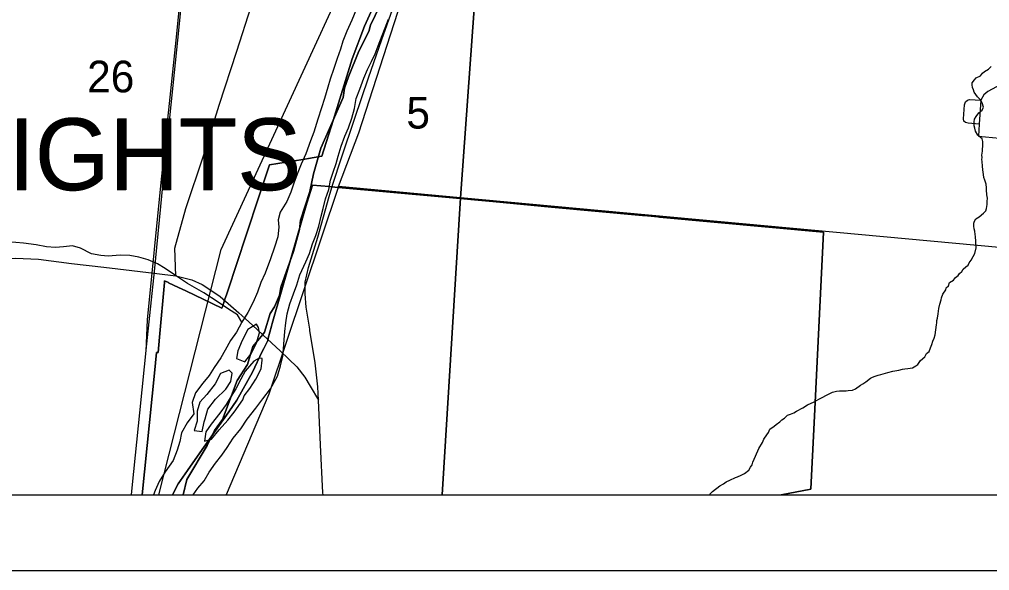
# Model space of a CAD drawing. Extents: x -38.1 to 35.9, y -2.7 to 28.5.
# Drawn here: x 9.239 to 10.521, y 12.831 to 13.559 of the extents above; entities that cross this region are included whole.
import ezdxf

# ---------------------------------------------------------------- set-up
doc = ezdxf.new("R2010")
doc.units = 0
for name, color, linetype in [('GM_X_City_Street', 7, 'Continuous'), ('GM_X_City_Street_Text', 7, 'Continuous'), ('GM_X_Corporation', 7, 'Continuous'), ('GM_X_Minor_River', 7, 'Continuous'), ('GM_X_Section', 7, 'Continuous'), ('GM_X_Township_Road', 7, 'Continuous'), ('GM_X_Township_Subdivision', 7, 'Continuous'), ('GM_X_US_Route', 7, 'Continuous'), ('SH_Border', 7, 'Continuous'), ('SH_Data', 7, 'Continuous')]:
    doc.layers.add(name, color=color, linetype=linetype)

msp = doc.modelspace()

# ---------------------------------------------------------------- linework, layer by layer
at = {"layer": 'GM_X_City_Street'}
for points in [[(9.4453, 13.22), (9.444, 13.2564), (9.4587, 13.3089), (9.4818, 13.3782), (9.5028, 13.4454), (9.5259, 13.5168), (9.5448, 13.5755), (9.5616, 13.6259), (9.57, 13.6511), (9.5825, 13.7036), (9.5952, 13.7624), (9.6045, 13.8015), (9.609, 13.8423), (9.6092, 13.8484)], [(10.5412, 13.4757), (10.5181, 13.4635), (10.5128, 13.4588), (10.509, 13.4517), (10.5066, 13.4204), (10.506, 13.4042), (10.5892, 13.3966)], [(10.5066, 13.4204), (10.492, 13.4214), (10.4888, 13.4225), (10.4866, 13.4243), (10.4862, 13.4271), (10.4875, 13.4459), (10.4886, 13.4497), (10.4911, 13.4517), (10.4938, 13.4527), (10.509, 13.4517)]]:
    msp.add_lwpolyline(points, dxfattribs=at)
at = {"layer": 'GM_X_City_Street_Text'}
msp.add_line((9.5328, 13.1674), (9.5467, 13.1547), dxfattribs=at)
for points in [[(9.6481, 13.3246), (9.6527, 13.3409), (9.6643, 13.3758), (9.6821, 13.428), (9.6998, 13.4814), (9.7174, 13.5322), (9.7316, 13.5717), (9.7554, 13.6313), (9.7764, 13.6835), (9.7943, 13.7255), (9.8058, 13.7523), (9.822, 13.7775), (9.8255, 13.7807)], [(9.6223, 13.1497), (9.6175, 13.1785), (9.6163, 13.1964), (9.6163, 13.2115), (9.6206, 13.2311), (9.6331, 13.2711), (9.6481, 13.3246)], [(9.1477, 13.2079), (9.1622, 13.217), (9.1854, 13.2292), (9.2042, 13.2375), (9.2179, 13.2418), (9.2336, 13.2434), (9.2638, 13.2418), (9.3078, 13.2364), (9.3504, 13.2313), (9.3871, 13.2268), (9.4204, 13.2231), (9.4453, 13.22)], [(9.4453, 13.22), (9.4666, 13.2146), (9.4801, 13.2087), (9.4969, 13.1975)], [(9.4969, 13.1975), (9.5041, 13.1928), (9.5287, 13.1712), (9.5328, 13.1674)], [(9.5467, 13.1547), (9.5605, 13.142), (9.5837, 13.1205), (9.6055, 13.1), (9.616, 13.0862), (9.623, 13.0741), (9.6337, 13.0559)], [(9.6337, 13.0559), (9.6331, 13.0735), (9.6297, 13.105), (9.6226, 13.1479), (9.6223, 13.1497)], [(9.64, 12.9308), (9.6398, 12.9336), (9.6365, 12.997), (9.6337, 13.0559)]]:
    msp.add_lwpolyline(points, dxfattribs=at)
at = {"layer": 'GM_X_Corporation'}
for points in [[(9.3869, 12.9308), (9.3883, 12.9446), (9.3979, 13.039), (9.4073, 13.1301), (9.4172, 13.2255), (9.4287, 13.3431), (9.4481, 13.5311), (9.4733, 13.7801), (9.4904, 13.9481), (9.5034, 14.0746), (9.5088, 14.1303), (9.5136, 14.1747), (9.5172, 14.2088), (9.5214, 14.251), (9.5248, 14.2842), (9.5323, 14.3467)], [(9.4062, 13.1203), (9.4081, 13.1617), (9.4262, 13.3434), (9.4457, 13.5313), (9.4708, 13.7803), (9.4879, 13.9484), (9.5009, 14.0749), (9.5064, 14.1306), (9.5111, 14.1749), (9.5147, 14.2091), (9.519, 14.2513), (9.5223, 14.2845), (9.5299, 14.347)]]:
    msp.add_lwpolyline(points, dxfattribs=at)
at = {"layer": 'GM_X_Section'}
for points in [[(10.4936, 13.2371), (10.4963, 13.2408), (10.4987, 13.2453), (10.501, 13.2495), (10.5027, 13.257), (10.5025, 13.2654), (10.5019, 13.2719), (10.5016, 13.2745), (10.5009, 13.2791), (10.5002, 13.2822), (10.4999, 13.2856), (10.4996, 13.2894), (10.5004, 13.292), (10.5024, 13.295), (10.5066, 13.298), (10.5124, 13.3028), (10.5155, 13.3058), (10.5163, 13.3088), (10.5172, 13.3141), (10.5173, 13.3183), (10.5177, 13.3225), (10.517, 13.3267), (10.5164, 13.3335), (10.5165, 13.3362), (10.5158, 13.3408), (10.514, 13.3461), (10.513, 13.3499), (10.5123, 13.3538), (10.5117, 13.3599), (10.511, 13.3648), (10.5107, 13.3709), (10.5104, 13.3736), (10.5105, 13.3762), (10.5102, 13.3793), (10.511, 13.3846), (10.5116, 13.3937), (10.5117, 13.3975), (10.5106, 13.4009), (10.508, 13.4032), (10.505, 13.4056), (10.5021, 13.411), (10.501, 13.4148), (10.5003, 13.4182), (10.5001, 13.4232), (10.5005, 13.427), (10.5029, 13.4303), (10.5064, 13.4352), (10.5106, 13.4385), (10.5126, 13.4427), (10.5108, 13.4484), (10.5079, 13.4527), (10.5045, 13.4565), (10.5023, 13.4592), (10.5001, 13.4623), (10.4994, 13.4654), (10.498, 13.4688), (10.4973, 13.4723), (10.4973, 13.4749), (10.5004, 13.4786), (10.5028, 13.4816), (10.5085, 13.4842), (10.5112, 13.4876), (10.5139, 13.4898), (10.5189, 13.4927), (10.5228, 13.4964)], [(9.5326, 13.1587), (9.5267, 13.1683), (9.5151, 13.1758), (9.5012, 13.1852), (9.4824, 13.1973), (9.461, 13.2099), (9.4464, 13.2197), (9.4314, 13.2295), (9.4213, 13.2358), (9.4089, 13.241), (9.3964, 13.2447), (9.3847, 13.2468), (9.3717, 13.2471), (9.3561, 13.2459), (9.3463, 13.2468), (9.3342, 13.249), (9.3195, 13.2565), (9.3089, 13.2594), (9.2971, 13.2581), (9.2865, 13.2572), (9.2747, 13.2582), (9.2611, 13.2611), (9.244, 13.263), (9.2239, 13.2649)], [(10.1503, 12.9308), (10.1507, 12.9315), (10.1546, 12.9352), (10.1639, 12.9426), (10.1688, 12.9452), (10.1723, 12.9478), (10.1773, 12.95), (10.1846, 12.9536), (10.1873, 12.9547), (10.1922, 12.9569), (10.1968, 12.9591), (10.2026, 12.9635), (10.2046, 12.9673), (10.2069, 12.9706), (10.2078, 12.9737), (10.2094, 12.9778), (10.2113, 12.982), (10.2125, 12.985), (10.2141, 12.9887), (10.2157, 12.9921), (10.2204, 13), (10.2224, 13.0042), (10.226, 13.0098), (10.2283, 13.0132), (10.2303, 13.0173), (10.2357, 13.0214), (10.2384, 13.0236), (10.2434, 13.0273), (10.2461, 13.0299), (10.2496, 13.0318), (10.2534, 13.0359), (10.2573, 13.0373), (10.2618, 13.0391), (10.2653, 13.0413), (10.2737, 13.0457), (10.2799, 13.0498), (10.2887, 13.0534), (10.2948, 13.0571), (10.2991, 13.0593), (10.3052, 13.0622), (10.3094, 13.0644), (10.3129, 13.0662), (10.3182, 13.0676), (10.322, 13.0683), (10.3311, 13.0681), (10.3338, 13.0685), (10.3395, 13.0691), (10.3433, 13.0706), (10.3499, 13.0754), (10.3529, 13.0772), (10.3572, 13.0802), (10.363, 13.085), (10.366, 13.0861), (10.3695, 13.0875), (10.3733, 13.0886), (10.3767, 13.0897), (10.3859, 13.0921), (10.3927, 13.0939), (10.4007, 13.0956), (10.4053, 13.0967), (10.4087, 13.097), (10.4125, 13.0977), (10.4186, 13.0983), (10.4229, 13.1013), (10.4259, 13.1027), (10.4291, 13.108), (10.4349, 13.1128), (10.4372, 13.1173), (10.4407, 13.1199), (10.4423, 13.1248), (10.4443, 13.1294), (10.4455, 13.1339), (10.4471, 13.1377), (10.4484, 13.1422), (10.4502, 13.1551), (10.4506, 13.1577), (10.451, 13.1611), (10.4515, 13.1642), (10.4524, 13.1699), (10.4536, 13.1767), (10.4549, 13.1824), (10.4565, 13.1884), (10.457, 13.1911), (10.4586, 13.1956), (10.4625, 13.2016), (10.4633, 13.2042), (10.466, 13.2068), (10.4676, 13.211), (10.473, 13.2143), (10.4753, 13.2177), (10.4792, 13.2203), (10.4808, 13.2229), (10.4839, 13.2255), (10.4854, 13.2289), (10.4893, 13.2318), (10.492, 13.2341), (10.4936, 13.2371)]]:
    msp.add_lwpolyline(points, dxfattribs=at)
at = {"layer": 'GM_X_Township_Road'}
msp.add_line((9.4181, 12.9365), (9.4158, 12.9308), dxfattribs=at)
for points in [[(9.6839, 13.5724), (9.678, 13.5577), (9.6712, 13.543), (9.666, 13.5298), (9.6628, 13.5192), (9.6587, 13.5068), (9.6543, 13.4939), (9.6494, 13.4796), (9.6462, 13.469), (9.6417, 13.4539), (9.6377, 13.4418), (9.6332, 13.4267), (9.6276, 13.4098), (9.6235, 13.3981), (9.6171, 13.3811), (9.6111, 13.3672), (9.6068, 13.3562), (9.6012, 13.3423), (9.5975, 13.3306), (9.592, 13.3182), (9.5833, 13.3039), (9.5805, 13.2941), (9.5814, 13.2842), (9.58, 13.2713), (9.5759, 13.2577), (9.5703, 13.2422), (9.5635, 13.2234), (9.5579, 13.2113), (9.5535, 13.1985), (9.5476, 13.1853), (9.5404, 13.1714), (9.5326, 13.1587), (9.5255, 13.1455), (9.5177, 13.1347), (9.5106, 13.1219), (9.5047, 13.1118), (9.4961, 13.099), (9.4894, 13.0885), (9.4813, 13.0784), (9.4715, 13.0653), (9.4671, 13.0529), (9.4694, 13.0376), (9.4605, 13.026), (9.453, 13.0125), (9.4505, 13.0012), (9.4472, 12.9898), (9.442, 12.9763), (9.4315, 12.9613), (9.4232, 12.9485), (9.4181, 12.9365)], [(9.6477, 13.3341), (9.6499, 13.3462), (9.6531, 13.3568), (9.6571, 13.3681), (9.66, 13.3779), (9.6637, 13.3912), (9.6685, 13.4044), (9.6736, 13.4153), (9.6781, 13.4281), (9.6814, 13.441), (9.6835, 13.4542), (9.6883, 13.4666), (9.6939, 13.481), (9.6987, 13.4926), (9.7038, 13.5028), (9.7086, 13.5133), (9.7126, 13.5235), (9.7182, 13.5371), (9.7222, 13.5476), (9.7266, 13.5589)], [(9.4682, 12.9308), (9.4747, 12.9395), (9.4829, 12.9492), (9.4896, 12.9605), (9.4978, 12.9728), (9.5064, 12.9833), (9.5134, 12.9934), (9.5212, 13.0058), (9.5314, 13.0181), (9.5396, 13.0309), (9.5513, 13.0451), (9.5602, 13.0574), (9.5704, 13.0709), (9.5798, 13.0874), (9.5835, 13.101), (9.5868, 13.1139), (9.5877, 13.1234), (9.5887, 13.1355), (9.5893, 13.1465), (9.5907, 13.1579), (9.5924, 13.1696), (9.5961, 13.1828), (9.6009, 13.196), (9.6054, 13.2081), (9.6094, 13.2213), (9.617, 13.2383), (9.6218, 13.2496), (9.6262, 13.2624), (9.6302, 13.2733), (9.6342, 13.2854), (9.6375, 13.2986), (9.64, 13.3088), (9.6433, 13.3217), (9.6477, 13.3341)], [(9.5519, 13.156), (9.5404, 13.149), (9.5329, 13.1344), (9.5273, 13.1208), (9.5256, 13.1109), (9.5365, 13.1065), (9.5447, 13.1163), (9.5514, 13.1302)], [(9.5514, 13.1302), (9.556, 13.1445), (9.5545, 13.1519), (9.5519, 13.156)], [(9.5483, 13.1074), (9.537, 13.094), (9.5311, 13.0835), (9.5248, 13.0707), (9.5185, 13.0609), (9.5118, 13.0501), (9.5036, 13.0385), (9.4923, 13.0242), (9.4849, 13.0141), (9.4832, 13.0016), (9.4927, 13.0045), (9.5025, 13.0168), (9.5141, 13.0295), (9.5227, 13.04), (9.534, 13.0561)], [(9.534, 13.0561), (9.5356, 13.0614), (9.543, 13.0711), (9.5512, 13.0835), (9.558, 13.097), (9.5597, 13.1084)], [(9.5597, 13.1084), (9.5595, 13.1108), (9.5557, 13.1113), (9.5483, 13.1074)], [(9.5161, 13.0952), (9.5043, 13.0909), (9.4972, 13.0773), (9.4866, 13.0631), (9.4773, 13.053), (9.4737, 13.0413), (9.4738, 13.028), (9.4698, 13.0156), (9.4804, 13.0146), (9.4829, 13.0271)], [(9.4829, 13.0271), (9.4841, 13.0313), (9.4878, 13.0441), (9.4979, 13.0572), (9.5115, 13.0702), (9.5181, 13.0803), (9.5199, 13.0913)], [(9.5199, 13.0913), (9.5161, 13.0952)]]:
    msp.add_lwpolyline(points, dxfattribs=at)
at = {"layer": 'GM_X_US_Route'}
for points in [[(8.1146, 17.8763), (8.1146, 12.9308), (14.9146, 12.9308)], [(8.6149, 12.9308), (9.4011, 12.9308), (9.4173, 13.0914), (9.4201, 13.1189), (9.4219, 13.1189), (9.4237, 13.139), (9.4303, 13.2111), (9.4305, 13.2134), (9.4305, 13.2134), (9.4356, 13.211), (9.4359, 13.2109), (9.4489, 13.2047), (9.4588, 13.2), (9.5063, 13.1774), (9.5064, 13.1774), (9.507, 13.1792), (9.5085, 13.1835), (9.5103, 13.1892), (9.5122, 13.195), (9.5148, 13.2028), (9.525, 13.2336), (9.5541, 13.3216), (9.569, 13.3665), (9.613, 13.3737), (9.6157, 13.3742), (9.6209, 13.375), (9.6382, 13.3779), (9.6532, 13.4251), (9.6784, 13.5066), (9.6945, 13.5497), (9.729, 13.6256)], [(9.729, 13.6256), (9.6945, 13.5497), (9.6784, 13.5066), (9.6532, 13.4251), (9.6382, 13.3779), (9.6209, 13.375), (9.6157, 13.3742), (9.613, 13.3737), (9.569, 13.3665), (9.5541, 13.3216), (9.525, 13.2336), (9.5148, 13.2028), (9.5122, 13.195), (9.5103, 13.1892), (9.5085, 13.1835), (9.507, 13.1792), (9.5064, 13.1774), (9.5063, 13.1774), (9.4588, 13.2), (9.4489, 13.2047), (9.4359, 13.2109), (9.4356, 13.211), (9.4305, 13.2134), (9.4305, 13.2134), (9.4303, 13.2111), (9.4237, 13.139), (9.4219, 13.1189), (9.4201, 13.1189), (9.4173, 13.0914), (9.4011, 12.9308), (9.4409, 12.9308), (9.4485, 12.9452), (9.4607, 12.963), (9.4771, 12.9862), (9.5155, 13.0403), (9.5261, 13.056), (9.5466, 13.0928), (9.5597, 13.1201), (9.5616, 13.124), (9.5668, 13.1347), (9.5675, 13.1375), (9.572, 13.1536), (9.5729, 13.1569), (9.5853, 13.2014), (9.6186, 13.316), (9.6262, 13.3398), (9.6478, 13.3378), (9.6479, 13.3378), (9.6556, 13.3371), (9.8015, 13.3237), (9.8641, 13.3179), (9.9418, 13.3108), (10.062, 13.2997), (10.064, 13.2995), (10.0823, 13.2978), (10.0843, 13.2976), (10.3012, 13.2777), (10.2888, 13.026), (10.2845, 12.9388), (10.2844, 12.9382), (10.245, 12.9308), (14.9146, 12.9308)], [(8.1146, 12.9308), (9.4553, 12.9308), (9.4601, 12.9512), (9.487, 12.9959), (9.4966, 13.0159), (9.5073, 13.0303), (9.5263, 13.0818), (9.54, 13.103), (9.547, 13.1265), (9.5603, 13.1425), (9.5627, 13.1454), (9.5701, 13.17), (9.5758, 13.1791), (9.5824, 13.1943), (9.5843, 13.2049), (9.601, 13.2519), (9.6087, 13.281), (9.6103, 13.2936), (9.6224, 13.3315), (9.6271, 13.3546), (9.6368, 13.3887), (9.6664, 13.4554), (9.6684, 13.4679), (9.6734, 13.4827), (9.6873, 13.5167), (9.7004, 13.5425), (9.7027, 13.5508), (9.7335, 13.6152)], [(9.7335, 13.6152), (9.7027, 13.5508), (9.7004, 13.5425), (9.6873, 13.5167), (9.6734, 13.4827), (9.6684, 13.4679), (9.6664, 13.4554), (9.6368, 13.3887), (9.6271, 13.3546), (9.6224, 13.3315), (9.6103, 13.2936), (9.6087, 13.281), (9.601, 13.2519), (9.5843, 13.2049), (9.5824, 13.1943), (9.5758, 13.1791), (9.5701, 13.17), (9.5627, 13.1454), (9.5603, 13.1425), (9.547, 13.1265), (9.54, 13.103), (9.5263, 13.0818), (9.5073, 13.0303), (9.4966, 13.0159), (9.487, 12.9959), (9.4601, 12.9512), (9.4553, 12.9308), (14.9146, 12.9308)]]:
    msp.add_lwpolyline(points, dxfattribs=at)
for points in [[(9.9774, 14.3179), (10.9021, 14.2317), (10.8148, 13.2312), (9.8216, 13.3229), (9.8758, 14.0725)], [(9.8758, 14.0725), (9.8216, 13.3229), (9.6605, 13.3377), (9.6873, 13.4088), (9.8043, 13.7716)], [(9.1306, 12.9308), (9.4231, 12.9308), (9.5052, 13.2546), (9.7737, 13.837), (9.1432, 13.8435)], [(9.4409, 12.9308), (10.245, 12.9308), (10.2844, 12.9382), (10.2845, 12.9388), (10.2888, 13.026), (10.3012, 13.2777), (10.0843, 13.2976), (10.0823, 13.2978), (10.064, 13.2995), (10.062, 13.2997), (9.9418, 13.3108), (9.8641, 13.3179), (9.8015, 13.3237), (9.6556, 13.3371), (9.6479, 13.3378), (9.6478, 13.3378), (9.6262, 13.3398), (9.6186, 13.316), (9.5853, 13.2014), (9.5729, 13.1569), (9.572, 13.1536), (9.5675, 13.1375), (9.5668, 13.1347), (9.5616, 13.124), (9.5597, 13.1201), (9.5466, 13.0928), (9.5261, 13.056), (9.5155, 13.0403), (9.4771, 12.9862), (9.4607, 12.963), (9.4485, 12.9452)], [(9.5121, 12.9308), (9.7971, 12.9308), (9.8216, 13.3229), (9.6605, 13.3377), (9.5683, 13.0637)], [(9.7971, 12.9308), (10.7975, 12.9308), (10.8148, 13.2312), (9.8216, 13.3229)]]:
    msp.add_lwpolyline(points, close=True, dxfattribs=at)
at = {"layer": 'SH_Border'}
msp.add_line((8.1146, 12.9308), (14.9146, 12.9308), dxfattribs=at)
at = {"layer": 'SH_Data'}
msp.add_line((8.0146, 12.8308), (15.0146, 12.8308), dxfattribs=at)

# ---------------------------------------------------------------- texts
at = {"layer": 'GM_X_Minor_River'}
for s, height, p in [('26', 0.04186, (9.3283, 13.4622)), ('5', 0.0419, (9.75, 13.4144))]:
    msp.add_text(s, height=height, rotation=0, dxfattribs=at).set_placement(p)
at = {"layer": 'GM_X_Township_Subdivision'}
for p in [(8.5694, 13.3329), (8.5702, 13.3333)]:
    msp.add_text('HUBER HEIGHTS', height=0.094697, rotation=0, dxfattribs=at).set_placement(p)

doc.saveas('drawing.dxf')
